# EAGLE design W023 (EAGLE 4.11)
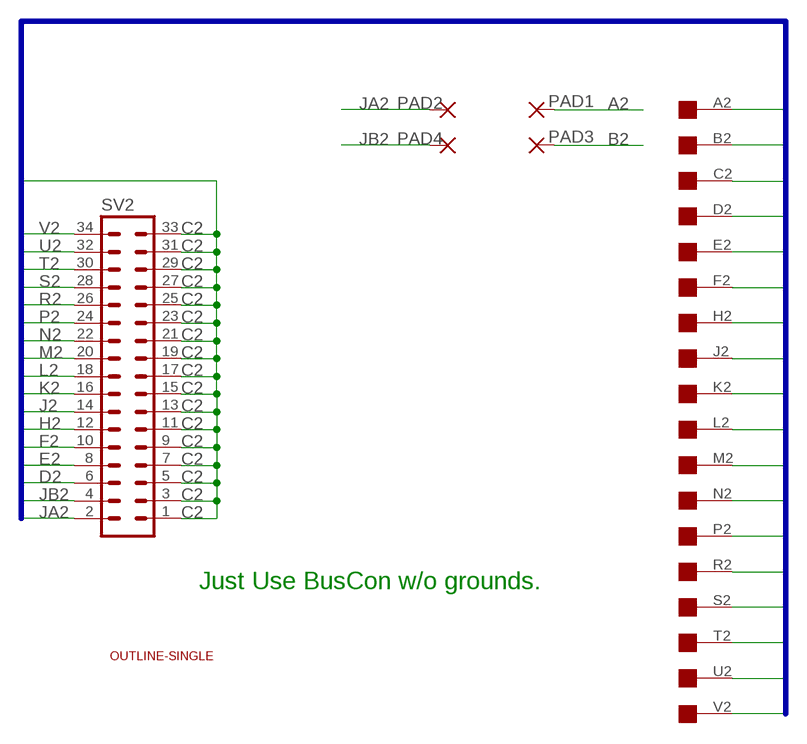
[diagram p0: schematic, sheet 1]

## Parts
PAD1  1,6/0,8  [1,6/0,8]
PAD2  1,6/0,8  [1,6/0,8]
PAD3  1,6/0,8  [1,6/0,8]
PAD4  1,6/0,8  [1,6/0,8]
SV2  MA17-2  [MA17-2]
U$1  EDGE-1  [EDGE-CON1]
U$2  OUTLINE-SINGLE  [SINGLE]

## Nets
A2: PAD1.1(P) U$1.A2
B2: PAD3.1(P) U$1.B2
C2: SV2.1 SV2.3 SV2.5 SV2.7 SV2.9 SV2.11 SV2.13 SV2.15 SV2.17 SV2.19 SV2.21 SV2.23 SV2.25 SV2.27 SV2.29 SV2.31 SV2.33 U$1.C2
D2: SV2.6 U$1.D2
E2: SV2.8 U$1.E2
F2: SV2.10 U$1.F2
H2: SV2.12 U$1.H2
J2: SV2.14 U$1.J2
JA2: PAD2.1(P) SV2.2
JB2: PAD4.1(P) SV2.4
K2: SV2.16 U$1.K2
L2: SV2.18 U$1.L2
M2: SV2.20 U$1.M2
N2: SV2.22 U$1.N2
P2: SV2.24 U$1.P2
R2: SV2.26 U$1.R2
S2: SV2.28 U$1.S2
T2: SV2.30 U$1.T2
U2: SV2.32 U$1.U2
V2: SV2.34 U$1.V2

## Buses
A2,B2,C2,D2,E2,F2,H2,J2,K2,L2,M2,N2,P2,R2,S2,T2,U2,V2

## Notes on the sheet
- Just Use BusCon w/o grounds.

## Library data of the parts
PAD1-PAD4 = wirepad:1,6/0,8: THROUGH-HOLE PAD
SV2 = con-lstb:MA17-2: PIN HEADER
U$1 = dec-con:EDGE-1: Single-Sided DEC Edge Connector -- (side 2)
U$2 = dec-con:OUTLINE-*: Board outlines for DEC boards.

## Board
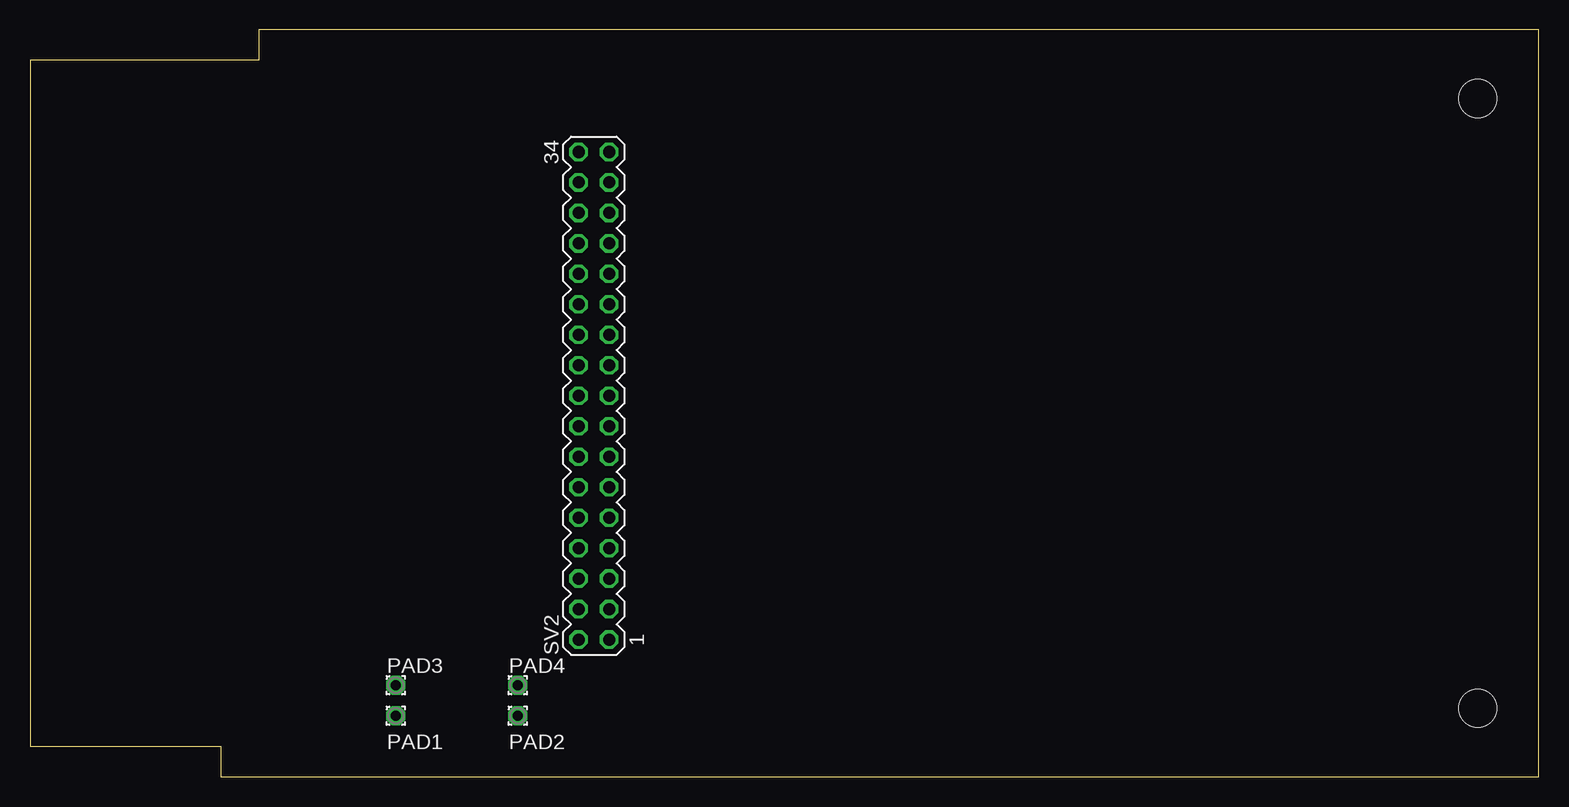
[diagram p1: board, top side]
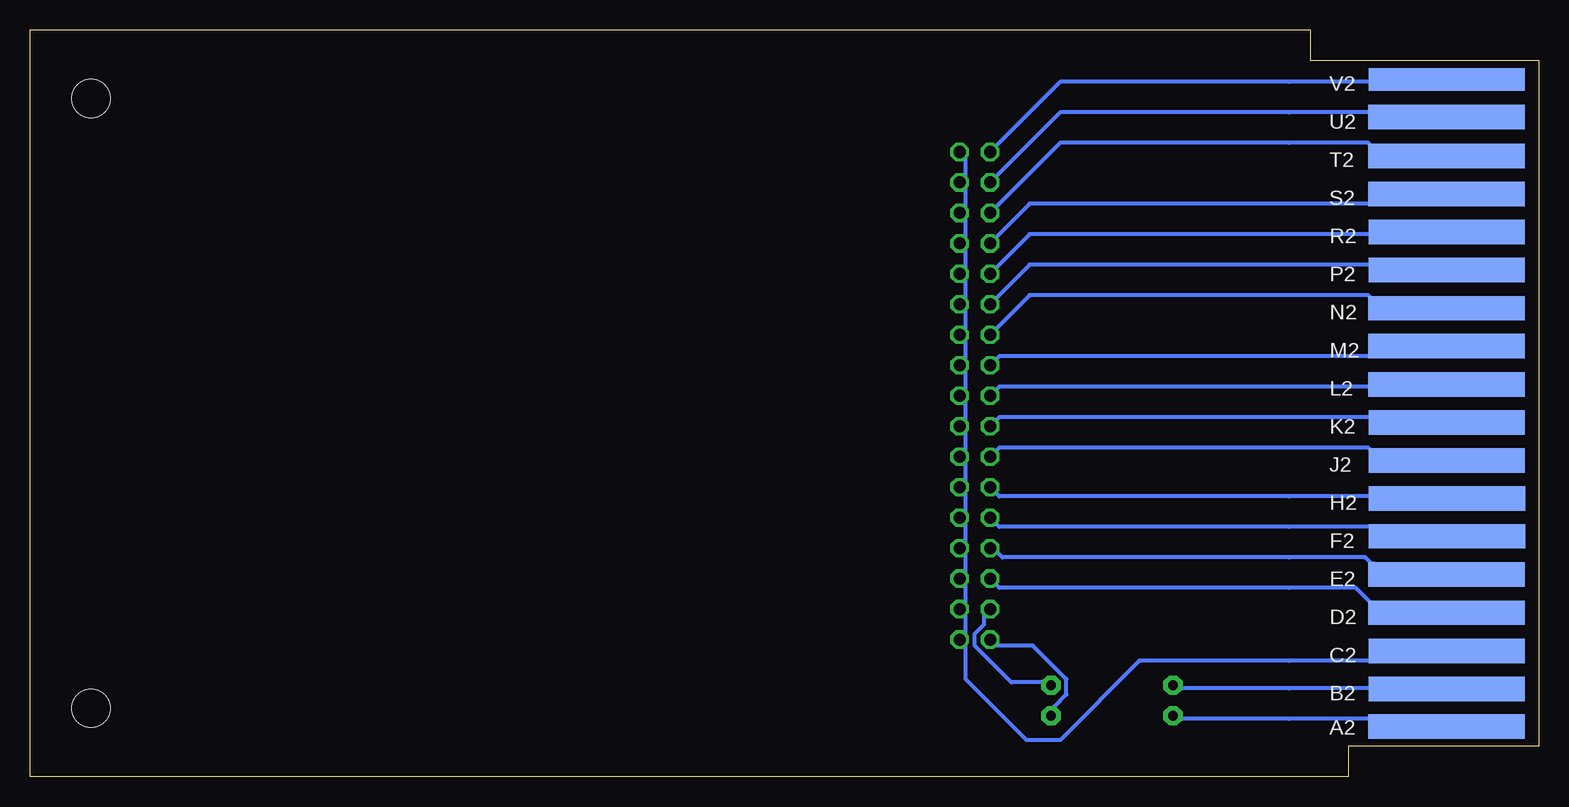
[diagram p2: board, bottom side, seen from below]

Size 125.73 x 62.23 mm. Coordinates in mm from the lower left corner, seen from the top.
Copper layers (1*16): Top 0.035mm / dielectric 1.5mm / Bottom 0.035mm
Design rules "10mils": minimum track width 13mil, minimum drill 28mil, track to track 10mil, track to pad 10mil, pad to pad 10mil, via to via 10mil, smd to smd 10mil, copper to edge 25mil, drill to drill 10mil, minimum pad ring 10mil, minimum via ring 8mil, stop-mask expansion 0mil, vias tented up to drill 0mil, thermal gap 10mil

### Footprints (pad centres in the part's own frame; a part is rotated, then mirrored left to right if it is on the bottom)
1,6/0,8 = drill 0.813 pad 1.6 octagon: 1 0,0
MA17-2 = drill 1.016 octagon: 1 -20.32,-1.27; 2 -20.32,1.27; 3 -17.78,-1.27; 4 -17.78,1.27; 5 -15.24,-1.27; 6 -15.24,1.27; 7 -12.7,-1.27; 8 -12.7,1.27; 9 -10.16,-1.27; 10 -10.16,1.27; 11 -7.62,-1.27; 12 -7.62,1.27; 13 -5.08,-1.27; 14 -5.08,1.27; 15 -2.54,-1.27; 16 -2.54,1.27; 17 0,-1.27; 18 0,1.27; 19 2.54,-1.27; 20 2.54,1.27; 21 5.08,-1.27; 22 5.08,1.27; 23 7.62,-1.27; 24 7.62,1.27; 25 10.16,-1.27; 26 10.16,1.27; 27 12.7,-1.27; 28 12.7,1.27; 29 15.24,-1.27; 30 15.24,1.27; 31 17.78,-1.27; 32 17.78,1.27; 33 20.32,-1.27; 34 20.32,1.27
EDGE-CON1 = smd 13.017 x 2.032 bottom: A2 7.69,4.194; B2 7.668,7.328; C2 7.668,10.49; D2 7.693,13.665; E2 7.693,16.84; F2 7.642,20.041; H2 7.642,23.19; J2 7.668,26.34; K2 7.668,29.515; L2 7.693,32.69; M2 7.693,35.89; N2 7.693,39.04; P2 7.668,42.24; R2 7.668,45.39; S2 7.693,48.565; T2 7.693,51.74; U2 7.693,54.966 | smd 13.017 x 1.905 bottom: V2 7.668,58.102
SINGLE = hole 3.175: 120.65,56.515; 120.65,5.715

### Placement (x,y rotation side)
PAD1  30.48,5.08 0 top
PAD2  40.64,5.08 0 top
PAD3  30.48,7.62 0 top
PAD4  40.64,7.62 0 top
SV2  46.99,31.75 90 top
U$1  0,0 0 top
U$2  0,0 0 top

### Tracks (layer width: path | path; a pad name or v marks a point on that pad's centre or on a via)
A2
  Bottom 0.33: PAD1.1 29.72,4.83 20.83,4.83 13.97,4.83 U$1.A2
B2
  Bottom 0.33: PAD3.1 29.72,7.37 20.83,7.37 13.97,7.37 U$1.B2
C2
  Bottom 0.33: SV2.33 47.75,51.56 47.75,50.04 SV2.31 47.75,49.02 47.75,47.5 SV2.29 47.75,46.48 47.75,44.96 SV2.27 47.75,43.94 47.75,42.42 SV2.25 47.75,41.4 47.75,39.88 SV2.23 47.75,38.86 47.75,37.34 SV2.21 47.75,36.32 47.75,34.8 SV2.19 47.75,33.78 47.75,32.26 SV2.17 47.75,31.24 47.75,29.72 SV2.15 47.75,28.7 47.75,27.18 SV2.13 47.75,26.16 47.75,24.64 SV2.11 47.75,23.62 47.75,22.1 SV2.9 47.75,21.08 47.75,19.56 SV2.7 47.75,18.54 47.75,17.78 47.75,17.02 SV2.5 47.75,16 47.75,14.48 SV2.3 47.75,13.46 47.75,11.94 SV2.1 47.75,10.92 47.75,8.13 42.67,3.05 39.88,3.05 33.27,9.65 20.83,9.65 13.97,9.65 U$1.C2
D2
  Bottom 0.33: SV2.6 45.21,16 44.96,15.75 20.83,15.75 15.24,15.75 13.97,14.48 U$1.D2
E2
  Bottom 0.33: SV2.8 45.21,18.8 44.7,18.29 20.83,18.29 14.48,18.29 13.97,17.78 U$1.E2
F2
  Bottom 0.33: SV2.10 45.21,21.08 44.96,20.83 20.83,20.83 13.97,20.83 U$1.F2
H2
  Bottom 0.33: SV2.12 45.21,23.62 44.96,23.37 20.83,23.37 13.97,23.37 U$1.H2
J2
  Bottom 0.33: SV2.14 45.21,27.18 44.96,27.43 20.83,27.43 14.22,27.43 13.97,27.18 U$1.J2
JA2
  Bottom 0.33: SV2.2 45.21,10.92 42.16,10.92 39.37,8.13 39.37,6.86 40.39,5.84 PAD2.1
JB2
  Bottom 0.33: SV2.4 46.23,13.46 46.23,12.7 46.99,11.94 46.99,10.92 43.94,7.87 41.4,7.87 PAD4.1
K2
  Bottom 0.33: SV2.16 45.21,29.72 44.96,29.97 20.83,29.97 13.97,29.97 U$1.K2
L2
  Bottom 0.33: SV2.18 45.21,32.26 44.96,32.51 20.83,32.51 13.97,32.51 U$1.L2
M2
  Bottom 0.33: SV2.20 45.21,34.8 44.96,35.05 20.83,35.05 13.97,35.05 U$1.M2
N2
  Bottom 0.33: SV2.22 45.21,37.34 42.42,40.13 20.83,40.13 14.22,40.13 13.97,39.88 U$1.N2
P2
  Bottom 0.33: SV2.24 45.21,39.88 42.42,42.67 20.83,42.67 13.97,42.67 U$1.P2
R2
  Bottom 0.33: SV2.26 45.21,42.42 42.42,45.21 20.83,45.21 13.97,45.21 U$1.R2
S2
  Bottom 0.33: SV2.28 45.21,44.96 42.42,47.75 20.83,47.75 13.97,47.75 U$1.S2
T2
  Bottom 0.33: SV2.30 45.21,47.5 39.88,52.83 20.83,52.83 14.22,52.83 13.97,52.58 U$1.T2
U2
  Bottom 0.33: SV2.32 45.21,50.04 39.88,55.37 20.83,55.37 13.97,55.37 U$1.U2
V2
  Bottom 0.33: SV2.34 45.21,52.58 39.88,57.91 20.83,57.91 13.97,57.91 U$1.V2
